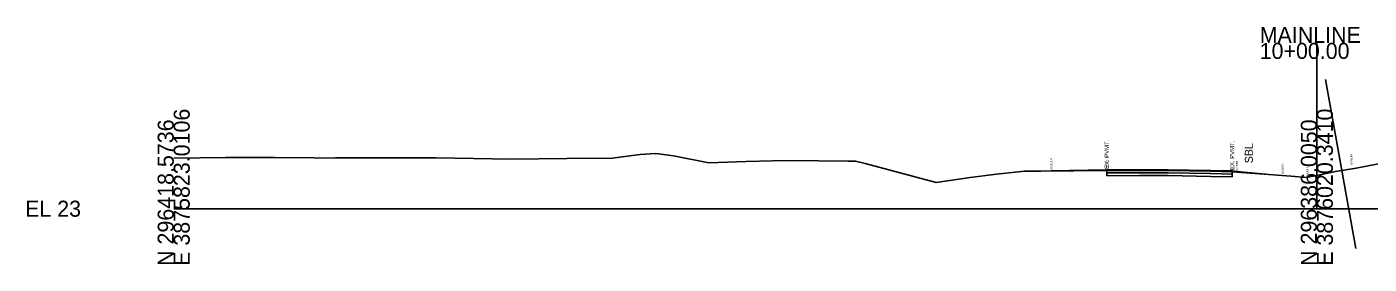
# Model space of a CAD drawing. Extents: x 14823 to 15251, y 114839 to 117377.
# Drawn here: x 14822.7 to 15057.5, y 114838.7 to 114880.1 of the extents above; entities that cross this region are included whole.
import ezdxf

# ---------------------------------------------------------------- set-up
doc = ezdxf.new("R2010")
doc.units = 0
for name, color, linetype in [('Default', 7, 'Continuous'), ('Level 1', 7, 'Continuous'), ('Level 10', 7, 'Continuous'), ('Level 2', 7, 'Continuous'), ('Level 3', 7, 'Continuous'), ('Level 42', 7, 'Continuous'), ('Level 53', 7, 'Continuous'), ('Level 56', 7, 'Continuous'), ('Level 59', 7, 'Continuous'), ('Level 63', 7, 'Continuous')]:
    doc.layers.add(name, color=color, linetype=linetype)

msp = doc.modelspace()

# ---------------------------------------------------------------- linework, layer by layer
at = {"layer": 'Default'}
msp.add_line((15049.86, 114870.97), (15055.18, 114841.38), dxfattribs=at)
at = {"layer": 'Level 1'}
for p, q in [((14925.05, 114857.19), (14929.95, 114857.82)), ((14929.95, 114857.82), (14932.71, 114858.02)), ((14932.71, 114858.02), (14935.83, 114857.6)), ((14935.83, 114857.6), (14941.96, 114856.4)), ((14848.36, 114857.21), (14857.48, 114857.33)), ((14857.48, 114857.33), (14865.99, 114857.33)), ((14865.99, 114857.33), (14872.91, 114857.23)), ((14872.91, 114857.23), (14873.44, 114857.22)), ((14873.44, 114857.22), (14876.67, 114857.24)), ((14876.67, 114857.24), (14889.43, 114857.28)), ((14889.43, 114857.28), (14894.27, 114857.26)), ((14894.27, 114857.26), (14907.37, 114857.04)), ((14907.37, 114857.04), (14917.15, 114857.11)), ((14917.15, 114857.11), (14925.05, 114857.19)), ((14941.96, 114856.4), (14948.5, 114856.63)), ((14948.5, 114856.63), (14953.1, 114856.73)), ((14953.1, 114856.73), (14955.98, 114856.79)), ((14955.98, 114856.79), (14966.38, 114856.69)), ((14966.38, 114856.69), (14967.66, 114856.68)), ((14967.66, 114856.68), (14969.31, 114856.27)), ((14969.31, 114856.27), (14981.75, 114852.96)), ((15051.64, 114854.84), (15055.25, 114855.46)), ((15055.25, 114855.46), (15059.13, 114856.19)), ((14981.75, 114852.96), (14987.71, 114853.79)), ((14987.71, 114853.79), (14992.33, 114854.41)), ((14992.33, 114854.41), (14997.19, 114854.94)), ((14997.19, 114854.94), (14999.72, 114854.94)), ((14999.72, 114854.94), (15000.07, 114854.94)), ((15000.07, 114854.94), (15011.61, 114855.02)), ((15011.61, 114855.02), (15017.34, 114855.06)), ((15017.34, 114855.06), (15022.33, 114855.06)), ((15022.33, 114855.06), (15029.75, 114854.91)), ((15029.75, 114854.91), (15033.53, 114854.83)), ((15033.53, 114854.83), (15043.88, 114854.02)), ((15043.88, 114854.02), (15046.51, 114853.8)), ((15046.51, 114853.8), (15047.16, 114853.93)), ((15047.16, 114853.93), (15048.36, 114854.17)), ((15048.36, 114854.17), (15051.64, 114854.84))]:
    msp.add_line(p, q, dxfattribs=at)
at = {"layer": 'Level 10'}
msp.add_line((15034.36, 114854.89), (15034.36, 114854.77), dxfattribs=at)
at = {"layer": 'Level 2'}
for p, q in [((15011.61, 114855.15), (15001.89, 114854.96)), ((15011.61, 114855.15), (15017.34, 114855.18)), ((15017.34, 114855.18), (15022.33, 114855.18)), ((15022.33, 114855.18), (15029.75, 114855.04)), ((15029.75, 114855.04), (15033.54, 114854.96)), ((15033.54, 114854.96), (15034.36, 114854.89))]:
    msp.add_line(p, q, dxfattribs=at)
at = {"layer": 'Level 3'}
msp.add_line((15034.36, 114854.89), (15039.36, 114854.38), dxfattribs=at)
at = {"layer": 'Level 59'}
for p, q in [((15011.61, 114855.02), (15011.61, 114854.61)), ((15011.61, 114854.61), (15017.34, 114854.64)), ((15011.61, 114854.61), (15011.61, 114854.11)), ((15011.61, 114854.11), (15017.34, 114854.14)), ((15017.34, 114854.64), (15022.33, 114854.64)), ((15017.34, 114854.14), (15022.33, 114854.14)), ((15022.33, 114854.64), (15029.75, 114854.49)), ((15022.33, 114854.14), (15029.75, 114853.99)), ((15029.75, 114854.49), (15033.53, 114854.42)), ((15029.75, 114853.99), (15033.53, 114853.92)), ((15033.53, 114854.42), (15033.53, 114854.83)), ((15033.53, 114853.92), (15033.53, 114854.42))]:
    msp.add_line(p, q, dxfattribs=at)
at = {"layer": 'Level 63'}
for p, q in [((15048.36, 114848.36), (15048.36, 114877.34)), ((14848.36, 114848.36), (15048.36, 114848.36)), ((15048.36, 114848.36), (15248.36, 114848.36))]:
    msp.add_line(p, q, dxfattribs=at)

# ---------------------------------------------------------------- texts
at = {"layer": 'Level 42'}
msp.add_text('SBL', height=1.4, rotation=90, dxfattribs=at).set_placement((15037.16, 114856.29))
at = {"layer": 'Level 53'}
for p in [(15011.98, 114855.02), (15033.91, 114854.83)]:
    msp.add_text(' EX. PVMT.', height=0.75, rotation=90, dxfattribs=at).set_placement(p)
at = {"layer": 'Level 56'}
for s, p in [('EOSLIN', (15054.55, 114856.07)), ('EOSLOUT', (15002.06, 114854.96)), ('EOPLOUT', (15011.78, 114855.15)), ('EOPRIN', (15034.54, 114854.89)), ('EOSRIN', (15042.54, 114854.49)), ('MEDDIT', (15046.85, 114853.78))]:
    msp.add_text(s, height=0.35, rotation=90, dxfattribs=at).set_placement(p)
at = {"layer": 'Level 63'}
for s, p in [('MAINLINE', (15038.37, 114877.34)), ('10+00.00', (15038.36, 114874.54)), ('EL 23', (14822.36, 114846.96))]:
    msp.add_text(s, height=2.8, dxfattribs=at).set_placement(p)
for s, p in [('E 3875823.0106', (14851.16, 114838.36)), ('E 3876020.3410', (15051.16, 114838.37)), ('N 296418.5736', (14848.36, 114838.36)), ('N 296386.0050', (15048.36, 114838.36))]:
    msp.add_text(s, height=2.8, rotation=90, dxfattribs=at).set_placement(p)

doc.saveas('drawing.dxf')
